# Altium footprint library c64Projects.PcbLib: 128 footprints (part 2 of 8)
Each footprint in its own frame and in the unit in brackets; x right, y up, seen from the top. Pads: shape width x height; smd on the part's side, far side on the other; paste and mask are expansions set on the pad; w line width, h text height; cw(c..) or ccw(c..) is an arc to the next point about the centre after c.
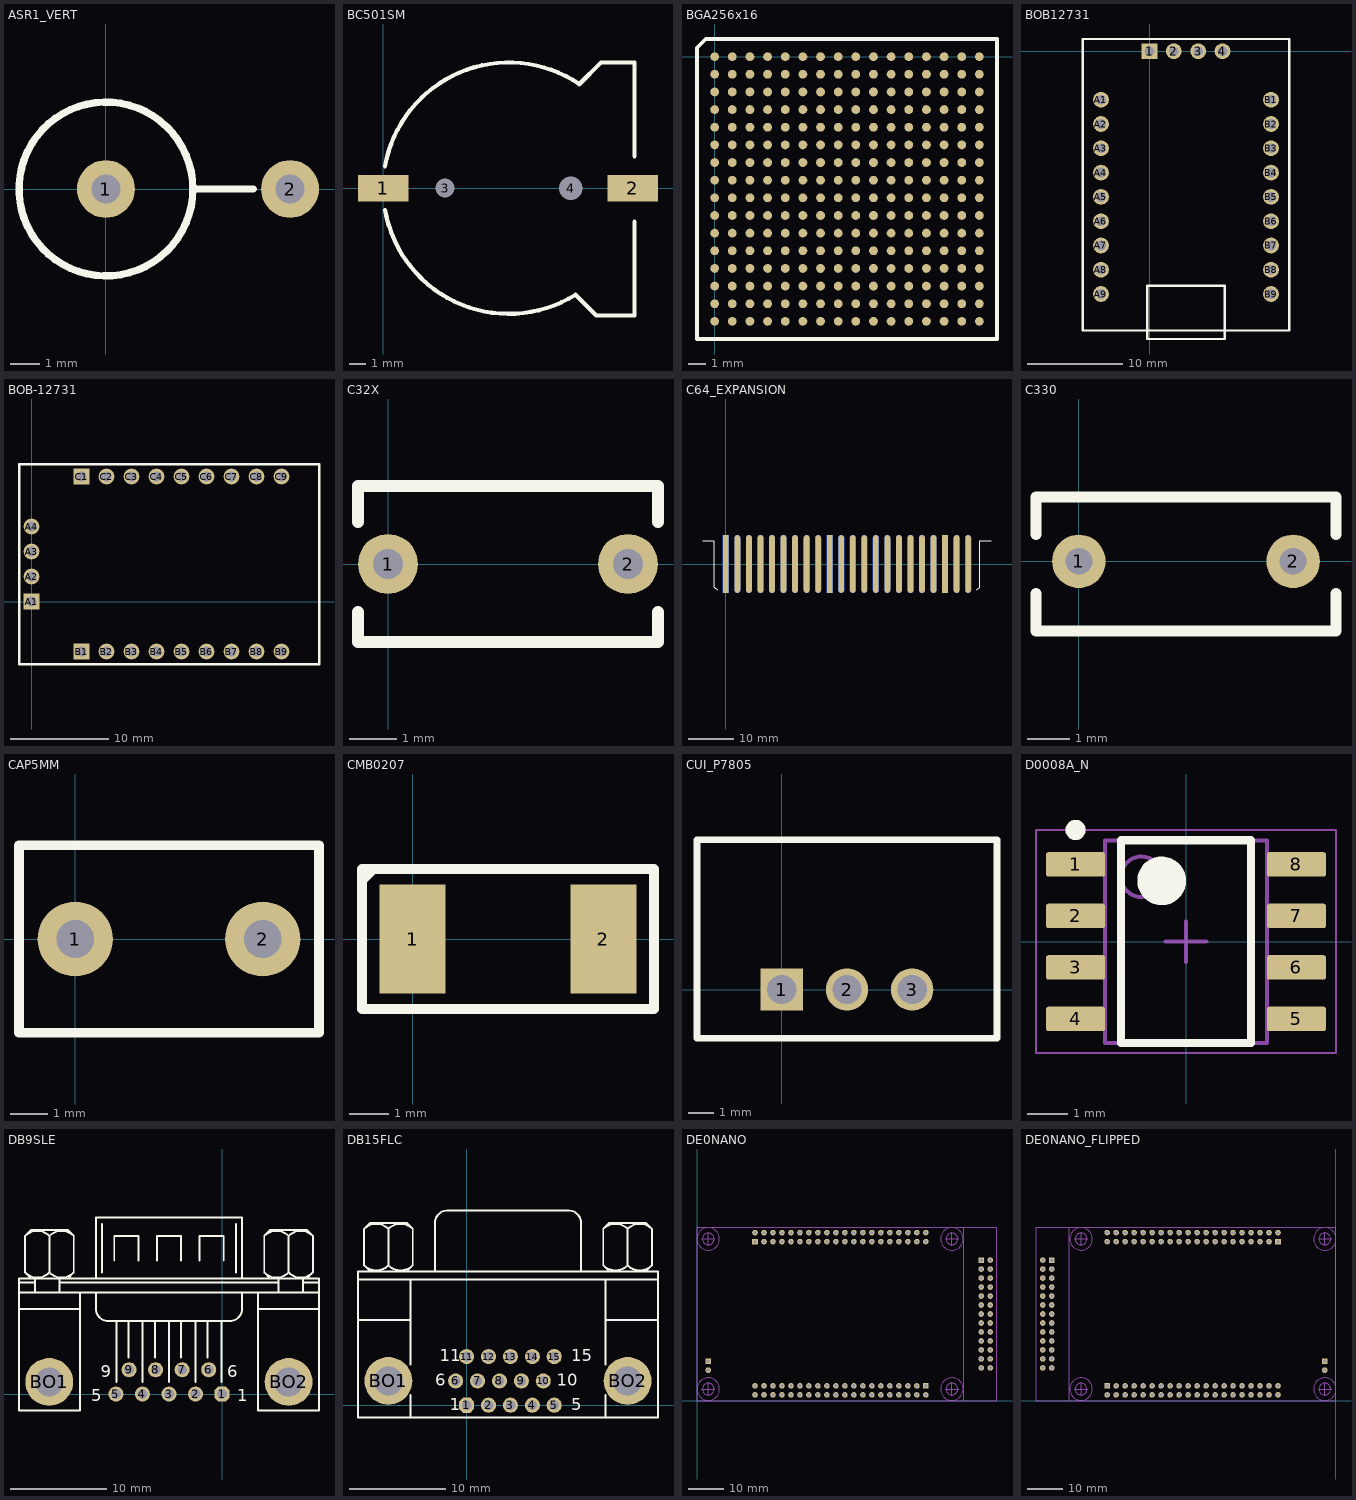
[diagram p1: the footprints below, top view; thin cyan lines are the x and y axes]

## ASR1_VERT [mm]
pads (2):
  round 2 hole 1: 1(0,0) 2(6.35,0)
Top Overlay:
  circle w0.254: c0,0 r3
  lines w0.254: 3,0 5.08,0

## BC501SM [mm]
pads (4):
  rect 3x1.6 smd mask+0.254: 1(0,0) 2(14.9,0)
  round 1 hole 1.14 unplated mask+0.254: 3(3.7,0)
  round 1 hole 1.4 unplated mask+0.254: 4(11.2,0)
Top Overlay:
  lines w0.254: 0.114,-1.302 ccw(c7.5,0) 11.474,-6.36 12.714,-7.6 15,-7.6 15,-2 ; 0.114,1.302 cw(c7.5,0) 11.694,6.218 ; 11.7,6.2 13,7.5 15,7.5 15,1.9

## BGA256x16 [mm]
pads (256):
  round 0.5 smd: A1(0,0) A2(1,0) A3(2,0) A4(3,0) A5(4,0) A6(5,0) A7(6,0) A8(7,0) A9(8,0) A10(9,0) A11(10,0) A12(11,0) A13(12,0) A14(13,0) A15(14,0) A16(15,0) B1(0,-1) B2(1,-1) B3(2,-1) B4(3,-1) B5(4,-1) B6(5,-1) B7(6,-1) B8(7,-1) B9(8,-1) B10(9,-1) B11(10,-1) B12(11,-1) B13(12,-1) B14(13,-1) B15(14,-1) B16(15,-1) C1(0,-2) C2(1,-2) C3(2,-2) C4(3,-2) C5(4,-2) C6(5,-2) C7(6,-2) C8(7,-2) C9(8,-2) C10(9,-2) C11(10,-2) C12(11,-2) C13(12,-2) C14(13,-2) C15(14,-2) C16(15,-2) D1(0,-3) D2(1,-3) D3(2,-3) D4(3,-3) D5(4,-3) D6(5,-3) D7(6,-3) D8(7,-3) D9(8,-3) D10(9,-3) D11(10,-3) D12(11,-3) D13(12,-3) D14(13,-3) D15(14,-3) D16(15,-3) E1(0,-4) E2(1,-4) E3(2,-4) E4(3,-4) E5(4,-4) E6(5,-4) E7(6,-4) E8(7,-4) E9(8,-4) E10(9,-4) E11(10,-4) E12(11,-4) E13(12,-4) E14(13,-4) E15(14,-4) E16(15,-4) F1(0,-5) F2(1,-5) F3(2,-5) F4(3,-5) F5(4,-5) F6(5,-5) F7(6,-5) F8(7,-5) F9(8,-5) F10(9,-5) F11(10,-5) F12(11,-5) F13(12,-5) F14(13,-5) F15(14,-5) F16(15,-5) G1(0,-6) G2(1,-6) G3(2,-6) G4(3,-6) G5(4,-6) G6(5,-6) G7(6,-6) G8(7,-6) G9(8,-6) G10(9,-6) G11(10,-6) G12(11,-6) G13(12,-6) G14(13,-6) G15(14,-6) G16(15,-6) H1(0,-7) H2(1,-7) H3(2,-7) H4(3,-7) H5(4,-7) H6(5,-7) H7(6,-7) H8(7,-7) H9(8,-7) H10(9,-7) H11(10,-7) H12(11,-7) H13(12,-7) H14(13,-7) H15(14,-7) H16(15,-7) J1(0,-8) J2(1,-8) J3(2,-8) J4(3,-8) J5(4,-8) J6(5,-8) J7(6,-8) J8(7,-8) J9(8,-8) J10(9,-8) J11(10,-8) J12(11,-8) J13(12,-8) J14(13,-8) J15(14,-8) J16(15,-8) K1(0,-9) K2(1,-9) K3(2,-9) K4(3,-9) K5(4,-9) K6(5,-9) K7(6,-9) K8(7,-9) K9(8,-9) K10(9,-9) K11(10,-9) K12(11,-9) K13(12,-9) K14(13,-9) K15(14,-9) K16(15,-9) L1(0,-10) L2(1,-10) L3(2,-10) L4(3,-10) L5(4,-10) L6(5,-10) L7(6,-10) L8(7,-10) L9(8,-10) L10(9,-10) L11(10,-10) L12(11,-10) L13(12,-10) L14(13,-10) L15(14,-10) L16(15,-10) M1(0,-11) M2(1,-11) M3(2,-11) M4(3,-11) M5(4,-11) M6(5,-11) M7(6,-11) M8(7,-11) M9(8,-11) M10(9,-11) M11(10,-11) M12(11,-11) M13(12,-11) M14(13,-11) M15(14,-11) M16(15,-11) N1(0,-12) N2(1,-12) N3(2,-12) N4(3,-12) N5(4,-12) N6(5,-12) N7(6,-12) N8(7,-12) N9(8,-12) N10(9,-12) N11(10,-12) N12(11,-12) N13(12,-12) N14(13,-12) N15(14,-12) N16(15,-12) P1(0,-13) P2(1,-13) P3(2,-13) P4(3,-13) P5(4,-13) P6(5,-13) P7(6,-13) P8(7,-13) P9(8,-13) P10(9,-13) P11(10,-13) P12(11,-13) P13(12,-13) P14(13,-13) P15(14,-13) P16(15,-13) R1(0,-14) R2(1,-14) R3(2,-14) R4(3,-14) R5(4,-14) R6(5,-14) R7(6,-14) R8(7,-14) R9(8,-14) R10(9,-14) R11(10,-14) R12(11,-14) R13(12,-14) R14(13,-14) R15(14,-14) R16(15,-14) T1(0,-15) T2(1,-15) T3(2,-15) T4(3,-15) T5(4,-15) T6(5,-15) T7(6,-15) T8(7,-15) T9(8,-15) T10(9,-15) T11(10,-15) T12(11,-15) T13(12,-15) T14(13,-15) T15(14,-15) T16(15,-15)
Top Overlay:
  lines w0.2: -1,-16 -1,0.5 -0.5,1 16,1 16,-16 -1,-16

## BOB12731 [mil]
pads (22):
  rect 65x65 hole 40: 1(0,0)
  round 65 hole 40: 2(100,0) 3(200,0) 4(300,0) A1(-200,-200) A2(-200,-300) A3(-200,-400) A4(-200,-500) A5(-200,-600) A6(-200,-700) A7(-200,-800) A8(-200,-900) A9(-200,-1000) B1(500,-200) B2(500,-300) B3(500,-400) B4(500,-500) B5(500,-600) B6(500,-700) B7(500,-800) B8(500,-900) B9(500,-1000)
Top Overlay:
  lines w10: -275,-1150 575,-1150 575,50 -275,50 -275,-1150 ; -10,-1185 310,-1185 310,-965 -10,-965 -10,-1185

## BOB-12731 [mil]
pads (22):
  rect 63x63 hole 40: A1(0,0) B1(200,-200) C1(200,500)
  round 63 hole 40: A2(0,100) A3(0,200) A4(0,300) B2(300,-200) B3(400,-200) B4(500,-200) B5(600,-200) B6(700,-200) B7(800,-200) B8(900,-200) B9(1000,-200) C2(300,500) C3(400,500) C4(500,500) C5(600,500) C6(700,500) C7(800,500) C8(900,500) C9(1000,500)
Top Overlay:
  lines w10: -50,-250 -50,550 1150,550 1150,-250 -50,-250

## C32X [mil]
pads (2):
  round 50 hole 25: 1(0,0) 2(200,0)
Top Overlay:
  lines w10: -25,-40 -25,-65 225,-65 225,-40 ; -25,35 -25,65 225,65 225,35
3D body: height 259.84, standoff 0, extent 0,-62.2 200.79,62.99

## C64_EXPANSION [mil]
pads (44):
  rect 50x500 smd mask+10: A1(0,0) A10(900,0) A20(1900,0)
  oval 50x500 smd mask+10: A2(100,0) A3(200,0) A4(300,0) A5(400,0) A6(500,0) A7(600,0) A8(700,0) A9(800,0) A11(1000,0) A12(1100,0) A13(1200,0) A14(1300,0) A15(1400,0) A16(1500,0) A17(1600,0) A18(1700,0) A19(1800,0) A21(2000,0) A22(2100,0)
  rect 50x500 smd far side mask+10: B1(0,0) B10(900,0) B20(1900,0)
  oval 50x500 smd far side mask+10: B2(100,0) B3(200,0) B4(300,0) B5(400,0) B6(500,0) B7(600,0) B8(700,0) B9(800,0) B11(1000,0) B12(1100,0) B13(1200,0) B14(1300,0) B15(1400,0) B16(1500,0) B17(1600,0) B18(1700,0) B19(1800,0) B21(2000,0) B22(2100,0)
Top Overlay:
  lines w10: -200,200 -100,200 -100,-200 -75,-225 ; 2175,-225 2200,-200 2200,200 2300,200

## C330 [mil]
pads (2):
  round 50 hole 25: 1(0,0) 2(200,0)
Top Overlay:
  lines w10: -40,-30 -40,-65 240,-65 240,-30 ; -40,25 -40,60 240,60 240,25
3D body: height 359.84, standoff 0, extent 0,-62.99 200.79,59.06

## CAP5MM [mm]
pads (2):
  round 2 hole 1: 1(0,0) 2(5,0)
Top Overlay:
  lines w0.254: -1.5,-2.5 -1.5,2.5 6.5,2.5 6.5,-2.5 -1.5,-2.5

## CMB0207 [mm]
pads (2):
  rect 1.7x2.8 smd: 1(0,0) 2(4.9,0)
Top Overlay:
  lines w0.254: -1.3,1.5 -1,1.8 ; -1.3,-1.8 6.2,-1.8 6.2,1.8 -1.3,1.8 -1.3,-1.8
3D body: height 1.52, standoff -1.52, extent 0.889,-1.518 4.064,1.518
3D body: height 1.52, standoff -1.52, extent 4.064,-1.512 5.029,1.524
3D body: height 1.52, standoff -1.52, extent -0.076,-1.524 0.889,1.512

## CUI_P7805 [mil]
pads (3):
  rect 65x65 hole 45: 1(0,0)
  round 65 hole 45: 2(100,0) 3(200,0)
Top Overlay:
  lines w10: -130,-75 -130,230 330,230 330,-75 -130,-75

## D0008A_N [mm] "SOIC, 8-Leads, Body 5x4mm, Pitch 1.27mm, IPC Medium Density"
height 1.75
pads (8):
  rrect17% 1.45x0.6 smd: 1(-2.725,1.905) 2(-2.725,0.635) 3(-2.725,-0.635) 4(-2.725,-1.905) 5(2.725,-1.905) 6(2.725,-0.635) 7(2.725,0.635) 8(2.725,1.905)
Top Overlay:
  circle w0.25: c-2.725,2.755 r0.125
  circle w0.6: c-0.6,1.5 r0.3
  lines w0.2: -1.6,-2.5 -1.6,2.5 1.6,2.5 1.6,-2.5 -1.6,-2.5
Outline:
  text ".Designator" at -1.397,-0.254 h0.6
3D Top:
  circle w0.1: c-1.1,1.6 r0.5
  lines w0.1: -2,-2.5 -2,2.5 2,2.5 2,-2.5 -2,-2.5
Courtyard Top:
  lines w0.05: -3.7,-2.75 -3.7,2.75 3.7,2.75 3.7,-2.75 -3.7,-2.75
  lines w0.1: -0.5,0 0.5,0 ; 0,-0.5 0,0.5
3D body: height 1.63, standoff 0, extent -3,-2.45 3,2.45

## DB9SLE [mil]
pads (11):
  oct 62x62 hole 40: 1(0,0)
  round 62 hole 40: 2(-109.17,0) 3(-218.33,0) 4(-327.5,0) 5(-436.67,0) 6(-55,100) 7(-164.17,100) 8(-273.33,100) 9(-382.5,100)
  round 196.67 hole 118.33: BO1(-710.83,50) BO2(273.33,50)
Top Overlay:
  lines w8: -835,350 -585,350 ; -835,416.67 398.33,416.67 ; -835,458.33 -768.33,458.33 ; -810.09,499.91 ccw(c-760,550) -709.91,499.91 ; -810.09,650.09 cw(c-760,600) -709.91,650.09 ; -785,475 -810,500 -810,650 -785,675 -635,675 -610,650 -610,500 -635,475 ; -768.33,416.67 -768.33,475 ; -710.09,499.91 ccw(c-660,550) -609.91,499.91 ; -710.09,650.09 cw(c-660,600) -609.91,650.09 ; -710,500 -710,650 ; -668.33,416.67 -668.33,475 ; -668.33,458.33 231.67,458.33 ; -585,416.67 -585,-66.67 -835,-66.67 -835,475 398.33,475 398.33,-66.67 148.33,-66.67 148.33,416.67 ; -518.33,416.67 -518.33,350 ccw(c-468.33,350) -468.33,300 31.67,300 ccw(c31.67,350) 81.67,350 81.67,416.67 ; -518.33,475 -518.33,725 81.67,725 81.67,475 ; -493.33,500 -493.33,700 ; -443.33,550 -443.33,650 -343.33,650 -343.33,550 ; -435,50 -435,300 ; -385,150 -385,300 ; -326.67,50 -326.67,300 ; -276.67,150 -276.67,300 ; -268.33,550 -268.33,650 -168.33,650 -168.33,550 ; -218.33,50 -218.33,300 ; -168.33,150 -168.33,300 ; -110,50 -110,300 ; -93.33,550 -93.33,650 6.67,650 6.67,550 ; -60,150 -60,300 ; -1.67,50 -1.67,300 ; 56.67,500 56.67,700 ; 148.33,350 398.33,350 ; 173.25,499.91 ccw(c223.33,550) 273.42,499.91 ; 173.25,650.09 cw(c223.33,600) 273.42,650.09 ; 198.33,475 173.33,500 173.33,650 198.33,675 348.33,675 373.33,650 373.33,500 348.33,475 ; 231.67,416.67 231.67,475 ; 273.25,499.91 ccw(c323.33,550) 373.42,499.91 ; 273.25,650.09 cw(c323.33,600) 373.42,650.09 ; 273.33,500 273.33,650 ; 331.67,416.67 331.67,475 ; 331.67,458.33 398.33,458.33
  text "9" at -498.33,70 h50
  text "5" at -538.33,-30 h50
  text "6" at 21.67,70 h50
  text "1" at 61.67,-30 h50

## DB15FLC [mil]
pads (17):
  oct 62x62 hole 40: 1(0,0)
  round 62 hole 40: 2(90,0) 3(180,0) 4(270,0) 5(360,0) 6(-45,100) 7(45,100) 8(135,100) 9(225,100) 10(315,100) 11(0,200) 12(90,200) 13(180,200) 14(270,200) 15(360,200)
  round 196.67 hole 118.33: BO1(-321.67,100) BO2(661.67,100)
Top Overlay:
  lines w8: -446.67,350 -230,350 ; -446.67,516.67 786.67,516.67 ; -421.75,574.91 ccw(c-371.67,625) -321.58,574.91 ; -421.75,725.09 cw(c-371.67,675) -321.58,725.09 ; -396.67,550 -421.67,575 -421.67,725 -396.67,750 -246.67,750 -221.67,725 -221.67,575 -246.67,550 ; -321.75,574.91 ccw(c-271.67,625) -221.58,574.91 ; -321.75,725.09 cw(c-271.67,675) -221.58,725.09 ; -321.67,575 -321.67,725 ; -230,-50 -230,41.67 ; -230,166.67 -230,350 ; -230,516.67 -230,350 ; -130,550 -130,750 cw(c-80,750) -80,800 420,800 cw(c420,750) 470,750 470,550 ; 561.58,574.91 ccw(c611.67,625) 661.75,574.91 ; 561.58,725.09 cw(c611.67,675) 661.75,725.09 ; 570,-50 570,41.67 ; 570,166.67 570,350 ; 570,516.67 570,350 ; 586.67,550 561.67,575 561.67,725 586.67,750 736.67,750 761.67,725 761.67,575 736.67,550 ; 661.58,574.91 ccw(c711.67,625) 761.75,574.91 ; 661.58,725.09 cw(c711.67,675) 761.75,725.09 ; 661.67,575 661.67,725 ; 786.67,350 570,350 ; -446.67,-50 786.67,-50 786.67,550 -446.67,550 -446.67,-50
  text "1" at -70,-20 h50
  text "6" at -130,80 h50
  text "11" at -110,180 h50
  text "15" at 430,180 h50
  text "10" at 370,80 h50
  text "5" at 430,-20 h50

## DE0NANO [mil]
pads (108):
  rect 62x62 hole 38: A1(640.16,1770.08) B1(2540.16,164.96) C1(3156.69,1564.96) D1(120.08,440.16)
  round 62 hole 38: A2(640.16,1870.08) A3(740.16,1770.08) A4(740.16,1870.08) A5(840.16,1770.08) A6(840.16,1870.08) A7(940.16,1770.08) A8(940.16,1870.08) A9(1040.16,1770.08) A10(1040.16,1870.08) A11(1140.16,1770.08) A12(1140.16,1870.08) A13(1240.16,1770.08) A14(1240.16,1870.08) A15(1340.16,1770.08) A16(1340.16,1870.08) A17(1440.16,1770.08) A18(1440.16,1870.08) A19(1540.16,1770.08) A20(1540.16,1870.08) A21(1640.16,1770.08) A22(1640.16,1870.08) A23(1740.16,1770.08) A24(1740.16,1870.08) A25(1840.16,1770.08) A26(1840.16,1870.08) A27(1940.16,1770.08) A28(1940.16,1870.08) A29(2040.16,1770.08) A30(2040.16,1870.08) A31(2140.16,1770.08) A32(2140.16,1870.08) A33(2240.16,1770.08) A34(2240.16,1870.08) A35(2340.16,1770.08) A36(2340.16,1870.08) A37(2440.16,1770.08) A38(2440.16,1870.08) A39(2540.16,1770.08) A40(2540.16,1870.08) B2(2540.16,64.96) B3(2440.16,164.96) B4(2440.16,64.96) B5(2340.16,164.96) B6(2340.16,64.96) B7(2240.16,164.96) B8(2240.16,64.96) B9(2140.16,164.96) B10(2140.16,64.96) B11(2040.16,164.96) B12(2040.16,64.96) B13(1940.16,164.96) B14(1940.16,64.96) B15(1840.16,164.96) B16(1840.16,64.96) B17(1740.16,164.96) B18(1740.16,64.96) B19(1640.16,164.96) B20(1640.16,64.96) B21(1540.16,164.96) B22(1540.16,64.96) B23(1440.16,164.96) B24(1440.16,64.96) B25(1340.16,164.96) B26(1340.16,64.96) B27(1240.16,164.96) B28(1240.16,64.96) B29(1140.16,164.96) B30(1140.16,64.96) B31(1040.16,164.96) B32(1040.16,64.96) B33(940.16,164.96) B34(940.16,64.96) B35(840.16,164.96) B36(840.16,64.96) B37(740.16,164.96) B38(740.16,64.96) B39(640.16,164.96) B40(640.16,64.96) C2(3256.69,1564.96) C3(3156.69,1464.96) C4(3256.69,1464.96) C5(3156.69,1364.96) C6(3256.69,1364.96) C7(3156.69,1264.96) C8(3256.69,1264.96) C9(3156.69,1164.96) C10(3256.69,1164.96) C11(3156.69,1064.96) C12(3256.69,1064.96) C13(3156.69,964.96) C14(3256.69,964.96) C15(3156.69,864.96) C16(3256.69,864.96) C17(3156.69,764.96) C18(3256.69,764.96) C19(3156.69,664.96) C20(3256.69,664.96) C21(3156.69,564.96) C22(3256.69,564.96) C23(3156.69,464.96) C24(3256.69,464.96) C25(3156.69,364.96) C26(3256.69,364.96) D2(120.08,340.16)
Mechanical 3:
  circle w10: c120.08,129.92 r65
  circle w10: c120.08,1800 r65
  circle w10: c2829.92,1800 r65
  circle w10: c2829.92,129.92 r65
  circle w10: c120.08,129.92 r125
  circle w10: c120.08,1800 r125
  circle w10: c2829.92,1800 r125
  circle w10: c2829.92,129.92 r125
  lines w10: 45.08,129.92 195.08,129.92 ; 45.08,1800 195.08,1800 ; 120.08,54.92 120.08,204.92 ; 120.08,1725 120.08,1875 ; 2754.92,129.92 2904.92,129.92 ; 2754.92,1800 2904.92,1800 ; 2829.92,54.92 2829.92,204.92 ; 2829.92,1725 2829.92,1875 ; 2959.84,0 3331.69,0 3331.69,1929.92 2959.84,1929.92 ; 2959.84,0 2959.84,1929.92 ; 2959.84,0 0,0 0,1929.92 2959.84,1929.92

## DE0NANO_FLIPPED [mil]
pads (108):
  rect 62x62 hole 38: A1(-640.16,1770.08) B1(-2540.16,164.96) C1(-3156.69,1564.96) D1(-120.08,440.16)
  round 62 hole 38: A2(-640.16,1870.08) A3(-740.16,1770.08) A4(-740.16,1870.08) A5(-840.16,1770.08) A6(-840.16,1870.08) A7(-940.16,1770.08) A8(-940.16,1870.08) A9(-1040.16,1770.08) A10(-1040.16,1870.08) A11(-1140.16,1770.08) A12(-1140.16,1870.08) A13(-1240.16,1770.08) A14(-1240.16,1870.08) A15(-1340.16,1770.08) A16(-1340.16,1870.08) A17(-1440.16,1770.08) A18(-1440.16,1870.08) A19(-1540.16,1770.08) A20(-1540.16,1870.08) A21(-1640.16,1770.08) A22(-1640.16,1870.08) A23(-1740.16,1770.08) A24(-1740.16,1870.08) A25(-1840.16,1770.08) A26(-1840.16,1870.08) A27(-1940.16,1770.08) A28(-1940.16,1870.08) A29(-2040.16,1770.08) A30(-2040.16,1870.08) A31(-2140.16,1770.08) A32(-2140.16,1870.08) A33(-2240.16,1770.08) A34(-2240.16,1870.08) A35(-2340.16,1770.08) A36(-2340.16,1870.08) A37(-2440.16,1770.08) A38(-2440.16,1870.08) A39(-2540.16,1770.08) A40(-2540.16,1870.08) B2(-2540.16,64.96) B3(-2440.16,164.96) B4(-2440.16,64.96) B5(-2340.16,164.96) B6(-2340.16,64.96) B7(-2240.16,164.96) B8(-2240.16,64.96) B9(-2140.16,164.96) B10(-2140.16,64.96) B11(-2040.16,164.96) B12(-2040.16,64.96) B13(-1940.16,164.96) B14(-1940.16,64.96) B15(-1840.16,164.96) B16(-1840.16,64.96) B17(-1740.16,164.96) B18(-1740.16,64.96) B19(-1640.16,164.96) B20(-1640.16,64.96) B21(-1540.16,164.96) B22(-1540.16,64.96) B23(-1440.16,164.96) B24(-1440.16,64.96) B25(-1340.16,164.96) B26(-1340.16,64.96) B27(-1240.16,164.96) B28(-1240.16,64.96) B29(-1140.16,164.96) B30(-1140.16,64.96) B31(-1040.16,164.96) B32(-1040.16,64.96) B33(-940.16,164.96) B34(-940.16,64.96) B35(-840.16,164.96) B36(-840.16,64.96) B37(-740.16,164.96) B38(-740.16,64.96) B39(-640.16,164.96) B40(-640.16,64.96) C2(-3256.69,1564.96) C3(-3156.69,1464.96) C4(-3256.69,1464.96) C5(-3156.69,1364.96) C6(-3256.69,1364.96) C7(-3156.69,1264.96) C8(-3256.69,1264.96) C9(-3156.69,1164.96) C10(-3256.69,1164.96) C11(-3156.69,1064.96) C12(-3256.69,1064.96) C13(-3156.69,964.96) C14(-3256.69,964.96) C15(-3156.69,864.96) C16(-3256.69,864.96) C17(-3156.69,764.96) C18(-3256.69,764.96) C19(-3156.69,664.96) C20(-3256.69,664.96) C21(-3156.69,564.96) C22(-3256.69,564.96) C23(-3156.69,464.96) C24(-3256.69,464.96) C25(-3156.69,364.96) C26(-3256.69,364.96) D2(-120.08,340.16)
Mechanical 3:
  circle w10: c-120.08,129.92 r65
  circle w10: c-120.08,1800 r65
  circle w10: c-2829.92,1800 r65
  circle w10: c-2829.92,129.92 r65
  circle w10: c-2829.92,129.92 r125
  circle w10: c-2829.92,1800 r125
  circle w10: c-120.08,1800 r125
  circle w10: c-120.08,129.92 r125
  lines w10: -2904.92,129.92 -2754.92,129.92 ; -2904.92,1800 -2754.92,1800 ; -2829.92,54.92 -2829.92,204.92 ; -2829.92,1725 -2829.92,1875 ; -195.08,129.92 -45.08,129.92 ; -195.08,1800 -45.08,1800 ; -120.08,54.92 -120.08,204.92 ; -120.08,1725 -120.08,1875 ; -2959.84,0 -3331.69,0 -3331.69,1929.92 -2959.84,1929.92 ; -2959.84,0 -2959.84,1929.92 ; -2959.84,0 0,0 0,1929.92 -2959.84,1929.92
